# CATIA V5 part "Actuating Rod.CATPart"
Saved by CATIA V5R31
Part number: Actuating Rod
Bounding box of the stored display mesh (mm): x -17.5 to 17.5, y -11.818 to 195.322, z -21 to 21
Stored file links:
  D:\PROJECTS\Project 2021\US EDITION\CATIA V5 6R 2021\Resources\Part Files\c12_catia_v5_6r2021_prt\c12_catia_v5-6r2021 figr_12-26\Actuating Rod.CATPart
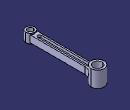
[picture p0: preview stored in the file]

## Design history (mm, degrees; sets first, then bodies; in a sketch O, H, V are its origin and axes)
Body1 (main body)
  Sketch1 on xy-plane, origin (0, 0, 0), H (1, 0, 0), V (0, 1, 0)
    arc A1 centre (0, 0) radius 12 from (-9, 7.9373) to (9, 7.9373) ccw
    arc A2 centre (0, 178) radius 17.5 from (13.5991, 166.9857) to (-13.5991, 166.9857) ccw
    point P1 (0, 178)
    line L1 (9, 154) -> (9, 7.9373)
    point P2 (9, 154)
    point P3 (9, 7.9373)
    arc A3 centre (29.6324, 154) radius 20.6324 from (9, 154) to (13.5991, 166.9857) cw
    point P5 (13.5991, 166.9857)
    point P6 (-13.5991, 166.9857)
    point P7 (-9, 154)
    arc A4 centre (-29.6324, 154) radius 20.6324 from (-9, 154) to (-13.5991, 166.9857) ccw
    point P9 (-9, 7.9373)
    line L2 (-9, 154) -> (-9, 7.9373)
    radius A2 = 17.5
    radius A1 = 12
    distance O P1 = 178
    distance V L1 = 9
    distance P1 P2 V = 24
    coincidence: P1 V
    vertical: L1 V
    tangency: A3 L1, A3 A2
    symmetry: P5 P6 V, P2 P7 V, A3 A4 V, P3 P9 V, L1 L2 V
  Pad1: profile Sketch1, direction (0, 0, 1), length 9, mirrored extent
  Sketch2 on xy-plane, origin (0, 0, 0), H (1, 0, 0), V (0, 1, 0)
    circle A1 centre (0, 0) radius 12
    reference projected arc E1 centre (0, 0) radius 12 from (-9, 7.9373) to (9, 7.9373) ccw from edge of Pad1
    reference projected arc E2 centre (0, 0) radius 12 from (-9, 7.9373) to (9, 7.9373) ccw from edge of Pad1
    reference projected arc E3 centre (0, 0) radius 12 from (-9, 7.9373) to (9, 7.9373) ccw from edge of Pad1
    concentricity: A1 E1, A1 E2
    tangency: A1 E3
  Pad2: profile Sketch2, direction (0, 0, 1), length 12, mirrored extent
  Sketch3 on xy-plane, origin (0, 0, 0), H (1, 0, 0), V (0, 1, 0)
    circle A1 centre (0, 178) radius 17.5
    point P1 (0, 178)
    reference projected arc E1 centre (0, 178) radius 17.5 from (13.5991, 166.9857) to (-13.5991, 166.9857) ccw from edge of Pad1
    reference projected arc E2 centre (0, 178) radius 17.5 from (13.5991, 166.9857) to (-13.5991, 166.9857) ccw from edge of Pad1
    coincidence: P1 V
    concentricity: A1 E1
    tangency: E2 A1
  Pad3: profile Sketch3, direction (0, 0, 1), length 21, mirrored extent
  Sketch4 on xy-plane, origin (0, 0, 0), H (1, 0, 0), V (0, 1, 0)
    circle A1 centre (0, 178) radius 12
    point P1 (0, 178)
    circle A2 centre (0, 0) radius 7.5
    reference projected circle E1 centre (0, 178) radius 17.5 from edge of Pad3
    radius A1 = 12
    radius A2 = 7.5
    coincidence: P1 V
    concentricity: A1 E1
  Pocket1: profile Sketch4, direction (0, 0, -1), length 21, mirrored extent
  Sketch5 on xy-plane, origin (0, 0, 0), H (1, 0, 0), V (0, 1, 0)
    construction line L1 (0, 24) -> (0, 154)
    point P1 (0, 24)
    line L2 (-5, 24) -> (-5, 154)
    line L3 (5, 154) -> (5, 24)
    arc A1 centre (0, 154) radius 5 from (-5, 154) to (5, 154) cw
    arc A2 centre (0, 24) radius 5 from (5, 24) to (-5, 24) cw
    length L1 = 130
    distance H P1 = 24
    radius A1 = 5
    coincidence: P1 V
    vertical: L1 V
    tangency: A1 L2, A2 L2, A1 L3, A2 L3
    parallelism: L1 L2
  Pocket2: profile Sketch5, direction (0, 0, -1), through (limit type 6), opposite side length -2.5
  Mirror1: of Pocket2, Sketch5, about xy-plane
